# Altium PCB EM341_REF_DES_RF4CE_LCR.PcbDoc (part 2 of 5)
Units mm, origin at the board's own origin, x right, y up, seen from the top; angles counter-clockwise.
Board outline 218.38 x 83.13 mm, 2 copper layers (Top Layer, Carbon Ink Layer); 111 components, 91 nets, 369 pads, 80 vias.
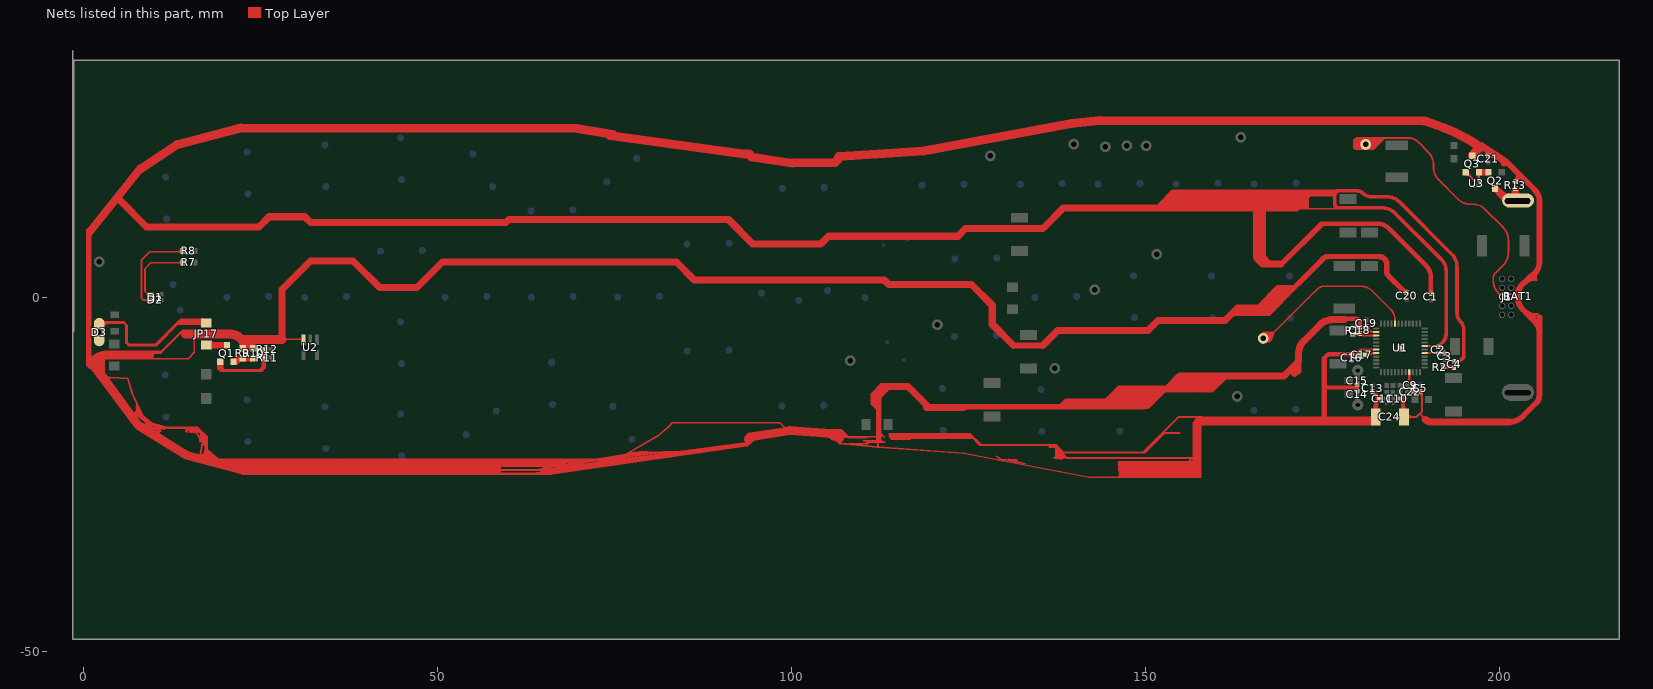
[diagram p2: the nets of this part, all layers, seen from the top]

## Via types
v1: diameter 1.2, hole 0, Top Layer to Carbon Ink Layer, 80 vias

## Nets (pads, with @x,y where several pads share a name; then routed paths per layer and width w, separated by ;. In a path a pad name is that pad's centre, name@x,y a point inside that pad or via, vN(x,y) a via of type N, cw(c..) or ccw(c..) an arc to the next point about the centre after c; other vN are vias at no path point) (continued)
1V8_39: C18.1 R1.2 U1.39 | length 6.6
  Top Layer w0.292: R1.2@179.19,-5.238 179.19,-5.242 cw(c179.419,-5.472) 179.419,-5.148 180.218,-5.148 cw(c180.218,-5.558) 180.508,-5.268 180.563,-5.323 ccw(c180.81,-5.075) 180.81,-5.425 U1.39@182.528,-5.425 ; R1.2@179.382,-5.352 cw(c179.874,-5.844) 179.874,-5.148 ccw(c179.874,-5.844) R1.2@179.382,-5.352 ; 179.829,-5.148 ccw(c179.829,-4.759) 180.104,-5.034 cw(c179.829,-4.759) 179.829,-5.148 ; 179.853,-5.148 cw(c179.853,-5.502) 180.104,-5.251 ccw(c179.853,-5.502) 179.853,-5.148 ; C18.1@180.255,-5.315 cw(c180.369,-5.711) 180.66,-5.42 ccw(c180.369,-5.711) C18.1@180.255,-5.315
BATT_NEG: BAT1.2 pad.51 pad.52 pad.53 pad.54 pad.55 pad.56 pad.57 pad.58 pad.59 pad.60 pad.61 pad.62 pad.63 pad.64 pad.65 pad.66 pad.67 pad.68 pad.69 pad.70 pad.71 pad.72 pad.73 pad.74 pad.75 pad.76 pad.77 pad.78 pad.79 pad.80 pad.81 pad.82 pad.83 pad.84 pad.85 pad.86 pad.87 pad.88 Q2.3 R13.2 | length 47.1
  Top Layer w1.016: Q2.3@199.308,15.388 200.319,14.376 ccw(c202.115,16.172) 202.115,13.632 BAT1.2@202.167,13.632 ; 200.044,14.651 ccw(c201.317,15.924) BAT1.2@201.317,14.124 ; BAT1.2@201.389,13.488 ccw(c200.266,15.022) R13.2@202.168,15.022 ; BAT1.2@201.498,13.496 ccw(c200.091,15.022) R13.2@202.168,15.022 ; BAT1.2@202.102,13.49 ccw(c201.946,13.647) BAT1.2@202.167,13.632 ; BAT1.2@202.567,13.632 202.475,13.632 202.25,13.632 BAT1.2@202.167,13.632 ; BAT1.2@202.772,14.079 cw(c203.206,15.022) R13.2@202.168,15.022 ; BAT1.2@202.881,13.492 cw(c204.166,15.022) R13.2@202.168,15.022 ; BAT1.2@201.826,13.499 ccw(c201.003,14.322) BAT1.2@202.168,14.322 ; BAT1.2@201.826,13.499 ccw(c201.003,14.322) BAT1.2@202.168,14.322 ; BAT1.2@201.826,13.499 ccw(c201.003,14.322) BAT1.2@202.168,14.322 ; BAT1.2@201.826,13.499 ccw(c201.003,14.322) BAT1.2@202.168,14.322 ; BAT1.2@202.167,13.632 ccw(c201.946,13.647) 202.168,13.647 R13.2@202.168,15.022 ; 200.446,14.249 ccw(c200.919,14.721) 201.148,14.094 cw(c200.919,14.721) 200.446,14.249 ; BAT1.2@201.576,13.499 ccw(c200.149,14.926) 202.168,14.926 cw(c200.149,14.926) BAT1.2@201.576,13.499 ; BAT1.2@201.651,13.499 ccw(c200.405,14.745) 202.168,14.745 cw(c200.405,14.745) BAT1.2@201.651,13.499 ; BAT1.2@201.676,13.499 ccw(c200.491,14.684) 202.168,14.684 cw(c200.491,14.684) BAT1.2@201.676,13.499 ; BAT1.2@201.751,13.499 ccw(c200.747,14.503) 202.168,14.503 cw(c200.747,14.503) BAT1.2@201.751,13.499 ; BAT1.2@201.776,13.499 ccw(c200.832,14.443) 202.168,14.443 cw(c200.832,14.443) BAT1.2@201.776,13.499 ; BAT1.2@201.951,13.499 ccw(c201.43,14.02) 202.168,14.02 cw(c201.43,14.02) BAT1.2@201.951,13.499 ; BAT1.2@202.001,13.499 ccw(c201.6,13.9) 202.168,13.9 cw(c201.6,13.9) BAT1.2@202.001,13.499 ; BAT1.2@202.168,14.057 ccw(c202.957,14.057) 202.399,13.499 cw(c202.957,14.057) BAT1.2@202.168,14.057 ; BAT1.2@202.168,14.238 ccw(c203.213,14.238) 202.474,13.499 cw(c203.213,14.238) BAT1.2@202.168,14.238 ; BAT1.2@202.168,14.479 ccw(c203.554,14.479) 202.574,13.499 cw(c203.554,14.479) BAT1.2@202.168,14.479 ; BAT1.2@202.168,14.6 ccw(c203.725,14.6) 202.624,13.499 cw(c203.725,14.6) BAT1.2@202.168,14.6 ; 202.168,14.781 ccw(c203.981,14.781) 202.699,13.499 cw(c203.981,14.781) 202.168,14.781 ; 202.168,14.841 ccw(c204.066,14.841) 202.724,13.499 cw(c204.066,14.841) 202.168,14.841
  Top Layer w1.27: BAT1.2@200.999,13.595 201.15,13.595 BAT1.2@201.335,13.595
GND: C1.2 C2.2 C3.2 C4.2 C5.2 C9.2 C10.2 C11.2 C13.2 C14.2 C15.2 C16.2 C17.2 C18.2 C19.2 C20.2 C21.2 C22.2 C24.1 C24.2 J1.5 Q3.3 R9.1 R10.1 R13.1 U1.9 U1.19 U1.38 U1.43 U1.49 U2.3 | length 2771.9
  Top Layer w0.254: 0.5,-9.56 0.44,-8.93 0.65,-9.64 1.17,-10.07 ; 0.5,9.47 7.73,18.45 ; 0.69,9.37 7.92,18.35 ; 0.72,8.5 0.834,8.756 ; 0.81,9.38 8.04,18.36 ; 0.83,9.28 8.06,18.26 ; 0.92,9.22 8.15,18.2 ; 1.02,9.2 8.25,18.18 ; 1.03,8.71 5.047,13.748 7.83,17.24 13.14,21.22 ; 1.62,10.05 0.86,9.37 3.75,12.75 ; 1.78,-9.24 1.91,-9.8 ; 2.01,-9.24 2.02,-10.01 ; 2.19,-9.01 2.27,-10.29 ; 2.44,-8.84 2.48,-10.6 ; 2.65,-8.8 2.67,-10.84 ; 2.88,-11.36 2.88,-8.7 ; 3.04,-11.38 3.74,-11.36 6.23,-11.52 6.82,-13.48 8.25,-16.61 9.53,-17.76 11.704,-18.432 ; 3.85,13.19 0.72,9.373 5.16,14.93 ; 4.38,12.97 0.834,8.756 ; 7.07,-8.197 7.342,-8.197 7.85,-7.69 10.97,-7.69 13.94,-4.72 14.61,-4.72 ; 7.47,-15.19 7.579,-15.485 ; 8.11,18.119 4.82,13.926 0.93,8.97 0.834,8.756 ; 8.82,-8.7 14.75,-8.7 15.64,-7.81 15.64,-6.01 16.427,-5.223 16.77,-5.223 ; 9.34,-7.9 10.93,-7.9 13.89,-4.94 ; 14.735,-18.602 16.112,-18.602 17.2,-19.69 17.2,-20.998 16.76,-20.558 16.76,-19.41 17.06,-19.71 17.06,-20.08 16.93,-19.95 16.93,-19.8 16.81,-19.68 ; 16.17,-18.84 16.49,-19.16 ; 16.43,-18.84 15.124,-18.84 14.957,-18.673 ; 16.798,-20.168 17.02,-20.39 ; 17.032,-19.31 17.412,-19.69 ; 17.2,-22.08 17.11,-21.57 17.06,-22.08 17.254,-22.358 ; 17.26,-21.321 17.412,-21.473 ; 17.328,-22.006 17.553,-22.444 ; 17.51,-22.96 17.448,-22.637 ; 17.59,-22.84 17.448,-22.637 ; 17.69,-22.71 17.553,-22.444 ; 18.534,-22.92 73.548,-22.92 ; 19.64,-23.08 36.12,-23.08 36.82,-23.78 21.13,-23.78 20.43,-23.08 ; 20.622,-23.272 36.032,-23.272 36.43,-23.67 21.71,-23.67 21.48,-23.44 21.29,-23.44 21.14,-23.29 21.14,-23.44 21.17,-23.47 36.04,-23.47 ; 21.36,-23.9 22.43,-24.97 66.083,-24.97 ; 27.85,-5.967 U2.3@31.054,-5.967 ; 36.16,-22.92 37.42,-24.18 37.94,-24.18 ; 36.48,-22.92 37.17,-23.61 38.84,-23.61 39.37,-23.08 ; 36.64,-23.08 71.766,-23.08 ; 36.838,-23.412 39.038,-23.412 ; 36.864,-23.304 39.146,-23.304 ; 37.1,-23.73 39.02,-23.73 39.41,-23.34 69.853,-23.34 ; 39.07,-23.78 67.224,-23.78 ; 39.19,-23.54 68.142,-23.54 ; 39.45,-23.22 69.893,-23.22 ; 57.04,-24.41 57.993,-24.767 ; 57.09,-24.41 57.09,-24.39 57.58,-23.9 67.749,-23.9 68.18,-23.77 76.325,-22.365 ; 57.36,-24.53 57.812,-24.7 57.993,-24.767 ; 57.47,-24.83 57.993,-24.767 ; 58.17,-24.66 58.4,-24.89 64.94,-24.89 ; 58.23,-24.41 64.49,-24.41 ; 58.41,-24.91 58.16,-24.83 57.993,-24.767 ; 64.01,-24.41 65.242,-24.13 ; 64.012,-24.838 91.85,-20.85 ; 64.75,-24.5 65.2,-24.76 71.435,-23.88 ; 64.854,-24.56 75.63,-23.12 83.85,-22.01 ; 64.96,-24.02 65.242,-24.13 ; 64.969,-24.898 65.18,-24.9 71.435,-23.88 ; 64.99,-24.92 64.49,-24.41 ; 65.066,-24.334 65.912,-24.968 93.75,-20.98 94.8,-20.09 ; 65.912,-24.868 93.75,-20.88 ; 69.47,-24.31 73.07,-23.83 ; 70.44,-23.38 75.847,-22.643 ; 72.66,-23.2 75.65,-22.758 ; 75.59,-22.793 75.65,-22.758 ; 79.11,-21.79 78.482,-21.895 ; 94.01,-20.53 64.49,-24.41 ; 94.45,-20.23 93.82,-20.72 88.087,-21.529 ; 99.26,-18.67 98.34,-17.75 83.15,-17.75 82.61,-18.29 81.17,-19.55 76.589,-22.212 ; 104.59,-19.194 104.906,-19.194 105.34,-18.76 107.01,-18.76 107.99,-19.74 ; 105.13,-19.79 105.84,-19.79 106.721,-20.671 107.034,-20.671 ; 106.26,-20.17 106.83,-20.65 107.034,-20.671 ; 106.74,-19.883 107,-19.51 107.99,-19.74 ; 106.96,-19.87 107.3,-19.76 107.98,-19.86 110.6,-19.88 ; 107.16,-19.4 106.89,-19.13 105.9,-19.13 105.71,-18.94 106.88,-18.94 107.5,-19.56 107.66,-19.56 ; 108.17,-20.71 110.77,-20.71 ; 110.1,-20.29 112.7,-20.29 ; 110.528,-20.478 113.128,-20.478 ; 111.45,-15.24 111.45,-13.61 ; 111.48,-13.61 112.73,-12.36 112.9,-12.36 ; 111.57,-15.23 111.83,-15.23 111.98,-15.08 111.98,-13.28 111.74,-13.52 111.74,-15.57 ; 111.62,-15.3 111.62,-13.67 ; 111.88,-15.63 111.88,-14 ; 111.98,-15.86 111.26,-15.14 111.26,-13.62 112.63,-12.25 113.32,-12.25 ; 112.07,-20.24 112.078,-20.29 112.108,-20.478 112.2,-21.05 ; 112.1,-19.74 107.99,-19.74 ; 112.24,-19.09 112.37,-19.09 113.04,-19.76 ; 112.45,-19.4 112.635,-19.585 112.865,-19.585 ; 112.505,-14.235 113.94,-12.8 114.85,-12.8 115.02,-12.63 ; 113.76,-19.36 125.228,-19.36 126.74,-20.872 126.74,-20.91 ; 113.81,-19.56 125.278,-19.56 ; 113.82,-19.65 125.288,-19.65 ; 113.83,-19.72 125.298,-19.72 ; 113.88,-19.79 125.348,-19.79 ; 113.92,-19.86 125.388,-19.86 ; 113.96,-19.93 125.428,-19.93 ; 114.09,-20.07 116.69,-20.07 ; 114.36,-19.86 116.96,-19.86 ; 114.36,-19.62 116.96,-19.62 ; 114.44,-19.45 117.04,-19.45 ; 125.42,-19.76 126.57,-20.91 137.38,-20.91 138.44,-21.97 149.86,-21.97 152.65,-19.18 154.74,-19.18 ; 128.91,-22.49 129.56,-22.94 130.18,-22.98 132.98,-23.54 130.59,-22.9 131.77,-23 ; 136.42,-21.19 137.15,-21.19 138.73,-22.77 ; 136.96,-22.7 138.46,-22.7 ; 137.11,-20.91 138.93,-22.73 156.985,-22.73 ; 137.336,-22.824 137.336,-21.376 ; 137.56,-22.83 137.56,-21.52 ; 137.705,-15.445 138.64,-14.51 ; 137.801,-22.779 137.801,-21.601 ; 137.95,-22.85 137.95,-21.94 ; 138.081,-22.689 138.081,-21.881 ; 138.22,-22.78 138.22,-22.22 ; 138.297,-15.096 141.012,-15.096 ; 138.396,-14.886 141.112,-14.886 ; 138.89,-15.5 144.86,-15.5 145.48,-14.88 ; 138.89,-14.9 144.44,-14.9 146.62,-12.72 ; 138.92,-15.29 144.83,-15.29 147.53,-12.59 ; 138.97,-15.72 144.83,-15.72 145.56,-14.99 ; 139.03,-14.7 144.35,-14.7 146.34,-12.71 ; 139.09,-15.11 144.75,-15.11 146.47,-13.39 146.47,-13.34 147.11,-12.7 ; 139.18,-14.51 144.28,-14.51 146.2,-12.59 152.82,-12.59 ; 140.53,-15.5 140.74,-15.29 ; 144.5,-15.11 146.83,-12.78 ; 145.64,-14.88 145.64,-14.37 147.26,-12.75 ; 146.13,-24.17 157.598,-24.17 ; 146.15,-23.7 157.618,-23.7 ; 146.15,-23.53 157.618,-23.53 ; 146.15,-23.4 157.618,-23.4 ; 146.15,-23.31 157.618,-23.31 ; 146.17,-24.01 157.638,-24.01 ; 146.17,-23.81 157.638,-23.81 ; 146.21,-24.56 157.678,-24.56 ; 146.21,-24.36 157.678,-24.36 ; 146.25,-25.31 157.718,-25.31 ; 146.25,-25.16 157.718,-25.16 ; 146.25,-24.96 157.718,-24.96 ; 146.28,-24.75 157.748,-24.75 ; 146.89,-14.81 146.89,-12.59 ; 149.55,-21.97 154.57,-16.95 157.98,-16.95 ; 153.87,-25.44 156.82,-22.49 157.225,-22.49 ; 157.007,-25.2 ccw(c157.481,-24.853) 157.827,-25.327 ; 157.518,-25.44 141.95,-25.44 124.24,-22.07 112.06,-21.19 107.034,-20.671 ; 169.22,4.31 175.29,10.38 176.27,10.38 ; 169.31,12.46 177.95,12.46 178.18,12.69 178.31,12.69 ; 170.25,12.46 172.6,14.81 172.9,14.81 ; 170.266,12.346 172.786,14.866 ; 170.462,12.672 170.932,12.672 ; 170.666,12.426 173.186,14.946 ; 170.702,12.672 172.84,14.81 ; 170.89,13.31 ccw(c170.98,13.89) 171.56,13.8 ; 171.025,12.445 173.575,14.995 ; 171.08,13.31 ccw(c171.17,13.89) 171.75,13.8 ; 171.33,13.28 ccw(c171.42,13.86) 172,13.77 ; 171.39,12.46 173.91,14.98 ; 171.62,12.46 172.72,13.56 172.72,12.59 172.71,12.6 172.05,12.6 172.57,13.12 ; 171.7,13.27 ccw(c171.79,13.85) 172.37,13.76 ; 171.84,13.15 ccw(c171.93,13.73) 172.51,13.64 ; 171.93,12.98 ccw(c172.02,13.56) 172.6,13.47 ; 171.94,12.69 ccw(c172.03,13.27) 172.61,13.18 ; 172.03,13.28 ccw(c172.12,13.86) 172.7,13.77 ; 172.04,12.57 ccw(c172.13,13.15) 172.71,13.06 ; 172.22,13.14 ccw(c172.31,13.72) 172.89,13.63 ; 172.46,13.01 172.46,12.82 172.56,12.72 172.56,12.87 ; 172.9,12.51 172.9,14.69 ; 172.9,14.77 173.17,15.04 ; 177.492,15.11 177.61,14.992 178.34,14.992 ; 188.823,-16.358 ccw(c189.523,-16.358) 189.028,-16.853 189.462,-17.287 ; R13.1@202.197,16.279 202.879,16.961 cw(c203.015,16.826) 203.015,17.017 ; 205.21,2.416 ccw(c205.178,0.017) 205.368,-2.376 ; 7.579,-15.485 7.966,-16.507 ; 7.579,-15.485 7.43,-15.58 7.9,-16.75 7.45,-16.04 7.45,-16.39 7.64,-16.69 7.21,-16.29 7.45,-16.61 9.28,-18.02 10.013,-18.248 ; 7.579,-15.485 7.95,-16.49 7.966,-16.507 ; 7.966,-16.507 8.5,-17.08 9.25,-17.8 11.6,-18.58 10.795,-18.6 ; 7.966,-16.507 8.16,-17.02 8.94,-17.64 10.245,-18.321 ; 10.013,-18.248 10.245,-18.321 ; 10.013,-18.248 10.523,-18.653 ; 10.013,-18.248 10.412,-18.712 ; 10.245,-18.321 10.82,-18.5 10.795,-18.6 ; 10.245,-18.321 10.78,-18.6 10.795,-18.6 ; 10.412,-18.712 10.583,-18.791 ; 10.412,-18.712 8.75,-17.94 10.66,-19.15 10.689,-19.033 ; 10.412,-18.712 10.689,-19.033 ; 10.523,-18.653 10.74,-18.825 ; 10.523,-18.653 10.583,-18.791 ; 10.583,-18.791 10.731,-18.86 ; 10.583,-18.791 10.689,-19.033 ; 10.689,-19.033 10.731,-18.86 ; 10.731,-18.86 10.86,-18.92 10.74,-18.825 ; 10.731,-18.86 10.74,-18.825 ; 10.74,-18.825 10.795,-18.6 ; 11.704,-18.432 11.86,-18.48 14.57,-18.55 14.957,-18.673 ; 11.704,-18.432 16.154,-18.432 17.412,-19.69 ; 14.957,-18.673 15.483,-18.84 16.49,-19.16 ; 15.627,-19.109 15.97,-19.22 16.46,-20.085 ; 15.627,-19.109 14.45,-18.73 14.45,-19.03 15.627,-19.109 ; 16.46,-20.085 16.62,-20.34 16.44,-20.44 16.46,-20.085 ; 16.46,-20.085 16.49,-19.54 16.76,-20.18 16.84,-20.37 16.794,-20.592 16.47,-22.15 16.77,-22.22 17.254,-22.358 ; 16.49,-19.16 16.76,-19.787 17.02,-20.39 ; 17.02,-20.39 17.121,-20.919 17.188,-21.271 ; 17.188,-21.271 17.408,-21.469 ; 17.188,-21.271 17.403,-22.401 ; 17.254,-22.358 17.403,-22.401 ; 17.254,-22.358 17.448,-22.637 ; 17.403,-22.401 17.448,-22.637 ; 17.403,-22.401 17.553,-22.444 ; 17.408,-21.469 17.412,-21.473 ; 17.408,-21.469 17.6,-22.23 17.908,-22.545 ; 17.408,-21.469 18.202,-22.349 ; 17.412,-21.473 19.021,-22.92 19.31,-23.18 18.959,-22.92 18.584,-22.642 ; 17.412,-21.473 17.412,-19.69 ; 17.553,-22.444 17.908,-22.545 ; 17.908,-22.545 18.241,-22.641 ; 17.908,-22.545 18,-22.64 18.241,-22.641 ; 18.202,-22.349 18.23,-22.38 18.584,-22.642 ; 18.202,-22.349 18.584,-22.642 ; 18.202,-22.349 17.63,-21.91 18.241,-22.641 ; 18.241,-22.641 18.584,-22.642 ; 30.529,-5.967 cw(c30.529,-6.562) U2.3@30.949,-6.142 ; 30.529,-5.967 cw(c30.529,-6.562) U2.3@30.949,-6.142 ; 30.529,-5.967 cw(c30.529,-6.562) U2.3@30.949,-6.142 ; 30.529,-5.967 cw(c30.529,-6.562) U2.3@30.949,-6.142 ; 65.242,-24.13 65.55,-24.06 66.506,-23.9 67.224,-23.78 ; 67.224,-23.78 71.404,-23.08 76.589,-22.212 ; 71.435,-23.88 88.087,-21.529 ; 71.435,-23.88 78.79,-23.01 87.3,-21.77 88.087,-21.529 ; 75.65,-22.758 75.847,-22.643 ; 75.65,-22.758 80.134,-22.095 ; 75.847,-22.643 76.325,-22.365 ; 75.847,-22.643 79.32,-22.17 80.134,-22.095 ; 76.325,-22.365 76.589,-22.212 ; 76.325,-22.365 78.783,-21.942 ; 76.589,-22.212 78.094,-21.96 ; 78.094,-21.96 78.783,-21.942 ; 78.094,-21.96 77.344,-21.98 78.482,-21.895 ; 78.094,-21.96 78.482,-21.895 ; 78.482,-21.895 79.488,-21.82 78.783,-21.942 ; 78.783,-21.942 78.976,-21.936 ; 78.976,-21.936 79.236,-21.972 ; 78.976,-21.936 79.97,-21.91 83.66,-21.77 80.134,-22.095 ; 78.976,-21.936 77.57,-22.26 79.236,-21.972 ; 79.236,-21.972 80.134,-22.095 ; R13.1@202.247,16.477 ccw(c202.247,16.834) 202.5,16.582 cw(c202.247,16.834) R13.1@202.247,16.477 ; R13.1@202.445,16.279 cw(c203.044,16.279) 202.62,16.702 ccw(c203.044,16.279) R13.1@202.445,16.279
  Top Layer w0.292: C17.2@180.035,-8.145 180.035,-7.677 cw(c180.209,-7.677) 180.086,-7.554 cw(c180.398,-7.866) 180.398,-7.425 U1.43@182.528,-7.425 ; C18.2@180.312,-4.415 cw(c180.355,-4.457) C18.2@180.355,-4.397 ; U1.38@182.528,-4.925 182.122,-4.925 cw(c182.122,-4.148) 181.572,-4.697 181.409,-4.534 ccw(c181.345,-4.598) 181.345,-4.507 181.312,-4.507 cw(c181.312,-4.286) 181.155,-4.443 ccw(c181.046,-4.551) 181.046,-4.397 C18.2@180.355,-4.397 ; C24.1@186.418,-16.927 188.223,-16.927 189.015,-16.135 189.015,-13.587 188.73,-13.303 188.73,-13.273 187.893,-13.273 187.838,-13.217 187.838,-12.512 187.618,-12.293 187.618,-12.025 ; U1.9@187.199,-10.497 187.199,-11.607 187.618,-12.025 ; U1.19@189.378,-6.925 191.24,-6.925 cw(c191.24,-7.01) C2.2@191.3,-6.95 ; C2.2@191.333,-6.989 cw(c191.293,-7.7) 191.796,-7.196 191.972,-7.372 cw(c191.417,-7.927) C3.2@192.202,-7.927 ; C18.2@180.355,-4.397 ccw(c180.355,-3.617) 180.99,-4.071 cw(c180.355,-3.617) C18.2@180.355,-4.397 ; C24.1@186.826,-17.306 cw(c187.739,-18.219) 187.739,-16.927 ; C24.1@186.826,-17.306 cw(c187.739,-18.219) 187.739,-16.927 ; C24.1@186.826,-17.306 cw(c187.739,-18.219) 187.739,-16.927 ; C24.1@186.826,-16.522 ccw(c187.804,-15.544) 187.804,-16.927 ; C24.1@186.826,-16.522 ccw(c187.804,-15.544) 187.804,-16.927 ; C24.1@186.826,-16.522 ccw(c187.804,-15.544) 187.804,-16.927 ; 187.618,-12.025 ccw(c187.942,-12.025) C9.2@187.827,-12.328 ; 187.618,-12.025 ccw(c187.942,-12.025) C9.2@187.827,-12.328 ; 187.618,-12.025 ccw(c187.942,-12.025) C9.2@187.827,-12.328 ; C22.2@187.713,-13.265 ccw(c187.412,-12.964) 187.838,-12.964 ; C22.2@187.713,-13.265 ccw(c187.412,-12.964) 187.838,-12.964 ; C22.2@187.713,-13.265 ccw(c187.412,-12.964) 187.838,-12.964 ; C9.2@187.713,-12.581 cw(c187.413,-12.881) 187.838,-12.881 ; C9.2@187.713,-12.581 cw(c187.413,-12.881) 187.838,-12.881 ; C9.2@187.713,-12.581 cw(c187.413,-12.881) 187.838,-12.881 ; 187.838,-13.04 ccw(c188.155,-13.04) C22.2@187.931,-13.265 ; 187.838,-13.04 ccw(c188.155,-13.04) C22.2@187.931,-13.265 ; 187.838,-13.04 ccw(c188.155,-13.04) C22.2@187.931,-13.265 ; 187.838,-12.806 cw(c188.156,-12.806) C9.2@187.931,-12.581 ; 187.838,-12.806 cw(c188.156,-12.806) C9.2@187.931,-12.581 ; 187.838,-12.806 cw(c188.156,-12.806) C9.2@187.931,-12.581 ; C22.2@187.931,-13.483 cw(c188.438,-13.991) 188.438,-13.273 ; C22.2@187.931,-13.483 cw(c188.438,-13.991) 188.438,-13.273 ; C22.2@187.931,-13.483 cw(c188.438,-13.991) 188.438,-13.273 ; 188.314,-13.273 cw(c188.314,-13.728) C5.2@188.636,-13.406 ; 188.314,-13.273 cw(c188.314,-13.728) C5.2@188.636,-13.406 ; 188.314,-13.273 cw(c188.314,-13.728) C5.2@188.636,-13.406 ; 188.433,-13.273 ccw(c188.433,-12.985) C5.2@188.636,-13.188 ; 188.433,-13.273 ccw(c188.433,-12.985) C5.2@188.636,-13.188 ; 188.433,-13.273 ccw(c188.433,-12.985) C5.2@188.636,-13.188 ; C5.2@188.636,-13.456 cw(c187.722,-14.371) 189.015,-14.371 ; C5.2@188.636,-13.456 cw(c187.722,-14.371) 189.015,-14.371 ; C5.2@188.636,-13.456 cw(c187.722,-14.371) 189.015,-14.371 ; C5.2@188.843,-13.249 cw(c188.427,-13.665) 189.015,-13.665 ; C5.2@188.843,-13.249 cw(c188.427,-13.665) 189.015,-13.665 ; C5.2@188.843,-13.249 cw(c188.427,-13.665) 189.015,-13.665 ; C17.2@179.938,-8.036 ccw(c179.705,-7.803) 180.035,-7.803 cw(c179.705,-7.803) C17.2@179.938,-8.036 ; 180.035,-7.744 ccw(c180.449,-7.744) 180.156,-8.036 cw(c180.449,-7.744) 180.035,-7.744 ; C18.2@180.321,-4.159 ccw(c180.898,-3.582) 180.898,-4.397 cw(c180.898,-3.582) C18.2@180.321,-4.159 ; C19.2@180.922,-4.397 ccw(c180.922,-4.023) 181.227,-4.241 cw(c180.922,-4.023) C19.2@180.922,-4.397 ; C19.2@181.267,-4.183 ccw(c181.625,-4.238) 181.369,-4.494 cw(c181.625,-4.238) C19.2@181.267,-4.183 ; C19.2@181.269,-4.16 ccw(c181.833,-4.16) 181.434,-4.559 cw(c181.833,-4.16) C19.2@181.269,-4.16 ; 190.762,-6.925 cw(c190.762,-7.535) 191.193,-7.104 ccw(c190.762,-7.535) 190.762,-6.925
  Top Layer w0.4: 138.63,-14.7 145.01,-14.7 ; 138.74,-14.51 145.13,-14.51 ; 144.07,-15.03 150.45,-15.03 ; 144.27,-14.81 150.65,-14.81 ; 144.43,-14.61 150.81,-14.61 ; 144.62,-14.47 151,-14.47 ; 144.77,-14.33 151.15,-14.33 ; 144.92,-14.21 151.3,-14.21 ; 145.14,-14.04 151.52,-14.04 ; 145.39,-13.84 151.77,-13.84 ; 145.59,-13.62 151.97,-13.62 ; 145.81,-13.39 152.19,-13.39 ; 146.28,-13.09 152.66,-13.09 ; 146.4,-12.83 152.78,-12.83
  Top Layer w0.508: 175.178,-12.77 179.85,-12.77 ; 176.6,14.69 176.902,14.992 179.828,14.992 cw(c179.828,13.808) 180.665,14.645 ccw(c181.83,15.81) 181.83,14.162 184.05,14.162 cw(c184.05,11.622) 185.846,13.419 193.2,6.065 cw(c191.404,4.269) 193.944,4.269 193.944,-2.224 ccw(c195.699,-2.224) 194.458,-3.465 cw(c193.407,-4.516) 194.893,-4.516 194.893,-8.313 cw(c194.388,-8.313) 194.745,-8.67 cw(c193.847,-7.772) 193.847,-9.042 C4.2@193.53,-9.042 ; 177.224,14.992 ccw(c177.224,14.611) 176.955,14.88 ccw(c177.589,14.246) 176.692,14.246 176.692,13.094 ccw(c177.222,13.094) 176.848,12.72 ccw(c177.173,13.046) 177.173,12.585 183.405,12.585 cw(c183.405,10.045) 185.201,11.841 191.747,5.296 cw(c190.169,3.718) 192.401,3.718 192.401,-5.187 cw(c190.628,-5.187) 191.881,-6.441 C2.2@191.302,-7.02 ; C16.2@179.085,-8.105 ccw(c179.185,-8) 179.185,-8.145 C17.2@180.035,-8.145 ; C15.2@179.857,-12.283 179.857,-13.275 C14.2@179.89,-13.275 ; C18.2@180.212,-4.242 180.851,-4.242 ccw(c180.851,-3.876) C19.2@181.11,-4.135 ; C10.2@185.926,-14.34 186.325,-14.34 186.325,-16.853 C24.1@186.48,-16.853 ; 180.806,-4.242 ccw(c180.806,-3.851) 181.082,-4.128 cw(c180.806,-3.851) 180.806,-4.242 ; C10.2@185.918,-14.373 cw(c184.937,-15.354) 186.325,-15.354 ccw(c184.937,-15.354) C10.2@185.918,-14.373 ; C24.1@186.119,-16.099 ccw(c185.62,-15.6) 186.325,-15.6 cw(c185.62,-15.6) C24.1@186.119,-16.099 ; 186.325,-15.074 ccw(c187.774,-15.074) 186.749,-16.099 cw(c187.774,-15.074) 186.325,-15.074
  Top Layer w0.635: 148.63,-15.51 150.28,-15.51 152.75,-13.04 ; 169.08,4.68 174.78,10.38 181.618,10.38 ; 175.178,-8.725 cw(c175.36,-8.725) 175.231,-8.596 175.593,-8.233 cw(c175.904,-8.544) 175.904,-8.105 C16.2@179.098,-8.105 ; 178.084,-3.19 ccw(c177.948,-2.741) 178.28,-3.073 179.612,-3.073 cw(c179.612,-3.929) 180.218,-3.323 ; C18.2@180.235,-4.242 180.235,-3.323 ; 181.372,10.372 182.595,10.372 cw(c182.595,7.832) 184.391,9.629 189.511,4.509 cw(c187.715,2.713) 190.255,2.713 C1.2@190.255,0.468 ; C13.2@182.027,-13.343 182.967,-14.282 cw(c182.941,-14.307) 182.977,-14.307 ccw(c184.227,-15.557) 182.46,-15.557 ; C24.2@182.46,-16.963 182.46,-15.557 ; J1.5@201.585,0.025 202.295,0.025 ccw(c202.295,0.17) 202.398,0.068 ; R13.1@202.197,16.279 ccw(c201.321,17.155) 202.56,17.155 202.56,17.195 ; 182.46,-15.557 cw(c181.666,-15.557) 182.21,-16.135 ccw(c181.666,-15.557) 182.46,-15.557 ; 182.46,-15.557 ccw(c183.207,-15.557) 182.721,-16.124 cw(c183.207,-15.557) 182.46,-15.557
  Top Layer w0.762: 162.48,-2.26 167.363,-2.26 169.081,-0.542 ; 165.07,-1.522 166.048,-1.522 ; 166.02,-1.35 168.69,1.32 170.93,1.32 ; 166.24,-1.65 167.973,-1.65 175.011,5.387 cw(c175.832,4.566) 175.832,5.727 182.865,5.727 cw(c182.865,4.515) 183.723,5.372 cw(c183.022,4.672) 184.012,4.672 184.012,3.639 ccw(c184.911,3.639) 184.276,3.003 186.497,0.782 ccw(c186.78,1.066) C20.2@186.78,0.665 ; 166.67,-1.65 ccw(c166.67,0.89) 168.466,-0.906 ; 167.084,-1.046 168.668,0.538 ; 167.634,-0.986 169.218,0.598 ; 167.874,-0.416 169.458,1.168 ; 168.042,-0.578 169.626,1.006 ; 168.514,-0.686 170.098,0.898 ; 175.164,-17.492 ccw(c175.049,-17.434) 175.178,-17.434 175.178,-8.725
  Top Layer w0.78: 202.94,1.55 204.16,2.77
  Top Layer w0.8: 0.72,-8.86 0.72,9.373 ; 4.006,12.947 4.798,13.946 8.11,18.119 ; 112.31,-20.24 112.31,-13.65 ; 123.99,-15.51 149.75,-15.51 152.28,-12.98 ; 131.317,-6.843 135.447,-6.843 ; 200.999,19.041 204.942,15.098 cw(c203.355,13.51) 205.6,13.51 205.6,5.055 cw(c203.06,5.055) 204.856,3.259 ; 201.388,-17.628 ccw(c201.388,-15.088) 203.184,-16.884 205.12,-14.948 ccw(c203.985,-13.813) 205.59,-13.813 205.59,-2.85 ; 202.5,0.38 cw(c204.082,0.38) 202.963,1.498 ; 202.5,0.39 202.511,0.166 ; 202.515,0.015 ccw(c205.055,0.015) 203.259,-1.781 204.846,-3.369 cw(c203.05,-5.165) 205.59,-5.165 ; 203.652,-2.177 ccw(c204.77,-1.058) 204.77,-2.64 ; 203.696,2.248 cw(c204.814,1.129) 204.814,2.711
  Top Layer w0.965: 204.344,2.746 204.856,3.259 ; 204.49,2.78 ccw(c204.066,3.49) 204.651,2.905
  Top Layer w1: 5.047,13.748 8.885,9.91 24.78,9.91 26.21,11.34 31.23,11.34 32.03,10.54 59.63,10.54 60.07,10.98 91.03,10.98 94.5,7.51 104.09,7.51 105.17,8.59 123.46,8.59 124.56,9.69 135.46,9.69 138.37,12.6 171.29,12.6 ; 28.02,-5.967 28.02,1.09 32.03,5.1 38.06,5.1 41.82,1.34 47.07,1.34 50.68,4.95 83.71,4.95 86.28,2.38 113.06,2.38 113.69,1.75 125.4,1.75 128.31,-1.16 128.31,-3.836 131.317,-6.843 ; 112.31,-13.65 113.33,-12.63 116.41,-12.63 119.33,-15.55 ; 119.02,-15.61 124.23,-15.61 ; 135.447,-6.843 137.57,-4.72 150.29,-4.72 151.712,-3.298 161.202,-3.298 162.978,-1.522 167.049,-1.522 ; 149.942,-15.318 152.28,-12.98 152.98,-12.98 154.8,-11.16 169.5,-11.16 ; 152.14,12.95 153.88,14.69 176.6,14.69 ; 153.06,-12.98 159.3,-12.98 160.93,-11.35 ; 153.08,13.2 171.32,13.2 ; 153.54,-12.44 159.78,-12.44 ; 153.83,13.91 172.134,13.91 ; 154.14,-11.82 160.38,-11.82 ; 165.62,13.27 165.62,5.56 166.5,4.68 169.08,4.68 ; 166.44,12.22 166.44,5.61 167.37,4.68 ; 169.579,-11.091 171.499,-9.171 ccw(c168.525,-8.505) 171.572,-8.505 171.572,-7.987 cw(c174.112,-7.987) 172.302,-6.206 ; 171.015,-10.775 171.15,-10.64 ; 171.36,-9.468 171.499,-9.329 171.42,-9.25 ; 171.49,-10.46 171.49,-9.148 ; 172.316,-6.191 174.574,-3.934 cw(c176.37,-5.73) 176.37,-3.19 178.084,-3.19 ; 200.743,19.11 200.78,19.11
  Top Layer w1.016: 189.462,-17.287 ccw(c190.283,-16.467) 190.283,-17.628 201.388,-17.628 ; 197.274,21.414 197.543,21.263 198.711,20.503 ; 198.679,20.513 200.548,19.298 200.62,18.96 ; C21.2@198.332,20.256 cw(c198.71,19.751) 199.054,20.28 ; C21.2@198.332,20.256 cw(c198.71,19.751) 199.054,20.28 ; C21.2@198.332,20.256 cw(c198.71,19.751) 199.054,20.28 ; C21.2@198.332,20.256 cw(c198.71,19.751) 199.054,20.28 ; C21.2@198.313,20.136 cw(c198.685,18.382) 199.662,19.885 ccw(c198.685,18.382) C21.2@198.313,20.136
  Top Layer w1.27: 8.11,18.119 13.179,21.508 22.194,23.879 69.654,23.791 74.784,22.974 74.307,22.817 93.231,20.227 93.985,20.205 94.287,19.794 100.125,18.897 106.143,18.991 106.465,19.345 106.65,19.825 118.595,20.638 139.491,24.511 143.482,24.91 189.345,24.873 192.105,23.905 193.64,23.247 195.45,22.295 196.71,21.565 ; 9.293,-8.197 3.317,-8.197 ; 14.371,-5.223 20.577,-5.223 ; 22.355,-5.967 28.02,-5.967 ; 58.405,-24.41 22.457,-24.41 14.511,-22.324 7.745,-18.145 1.568,-9.807 1.017,-9.5 0.998,-9.474 0.994,-9.469 1.521,-8.941 ; 93.904,-20.045 94.102,-19.772 99.663,-18.878 104.59,-19.194 105.613,-19.26 105.905,-19.593 106.412,-19.793 106.74,-19.883 ; 157.177,-24.905 ccw(c157.177,-24.837) 157.225,-24.885 157.225,-18.084 ; C24.2@182.407,-16.9 cw(c182.009,-16.9) 182.291,-17.182 182.203,-17.27 cw(c181.665,-16.733) 181.665,-17.492 158.025,-17.492 ; Q3.3@196.116,19.97 196.93,20.999 197.04,20.999 ; 1.521,-8.941 cw(c3.317,-10.737) 3.317,-8.197 ; 1.521,-8.941 cw(c3.317,-10.737) 3.317,-8.197 ; 1.521,-8.941 cw(c3.317,-10.737) 3.317,-8.197 ; 20.577,-5.223 cw(c20.577,-7.636) 22.283,-5.93 ; 20.577,-5.223 cw(c20.577,-7.636) 22.283,-5.93 ; 22.283,-5.93 22.328,-5.976 ; 22.328,-5.976 cw(c21.522,-6.783) R9.1@22.662,-6.783 ; 22.328,-5.976 cw(c21.522,-6.783) R9.1@22.662,-6.783 ; R9.1@22.662,-6.783 ccw(c23.188,-6.257) 23.188,-7 ; R9.1@22.662,-6.783 ccw(c23.188,-6.257) 23.188,-7 ; 23.188,-7 23.468,-7 ; 23.468,-7 ccw(c23.468,-6.573) R10.1@23.77,-6.875 ; 23.468,-7 ccw(c23.468,-6.573) R10.1@23.77,-6.875 ; R10.1@23.77,-6.875 ccw(c23.686,-6.791) R10.1@23.805,-6.791 ; R10.1@23.77,-6.875 ccw(c23.686,-6.791) R10.1@23.805,-6.791 ; R10.1@23.805,-6.791 cw(c24.742,-6.791) 24.079,-6.128 ; R10.1@23.805,-6.791 cw(c24.742,-6.791) 24.079,-6.128 ; 24.079,-6.128 cw(c24.467,-6.516) 24.467,-5.967 ccw(c24.467,-6.516) 24.079,-6.128 ; 157.225,-18.084 cw(c157.669,-18.084) 157.355,-17.77 ; 157.225,-18.084 cw(c157.669,-18.084) 157.355,-17.77 ; 157.355,-17.77 cw(c158.025,-18.44) 158.025,-17.492 ; 157.355,-17.77 cw(c158.025,-18.44) 158.025,-17.492
JCLK: J1.6 pad.0@181.04,21.55 | length 79.2
  Top Layer w0.254: 179.413,21.48 pad.0@180.503,21.48 ; 179.453,21.65 pad.0@180.543,21.65 ; 179.473,21.25 pad.0@180.563,21.25 ; 179.483,21.8 pad.0@180.573,21.8 ; 179.513,21.94 pad.0@180.603,21.94 ; 179.593,21.08 pad.0@180.683,21.08 ; 179.593,22.11 pad.0@180.683,22.11 ; 179.633,22.28 180.723,22.28 ; pad.0@180.663,22.207 cw(c181.009,21.733) pad.0@181.483,22.08 ; pad.0@180.933,21.73 182.023,21.73 ; pad.0@181.03,21.65 181.835,22.455 ; pad.0@181.103,21.05 182.193,21.05 ; pad.0@181.193,21.92 182.283,21.92 ; pad.0@181.313,21.24 182.403,21.24 ; 181.333,22.29 182.423,22.29 ; pad.0@181.343,22.15 182.433,22.15 ; pad.0@181.443,21.39 182.533,21.39 ; 181.523,22.32 182.613,22.32 ; pad.0@181.544,21.134 182.857,22.447 ; pad.0@181.573,21.53 182.663,21.53 ; pad.0@181.723,21.66 182.813,21.66 ; 181.883,21.78 182.973,21.78 ; 181.973,21.89 183.063,21.89 ; 182.083,22.02 183.173,22.02 ; 182.098,22.455 179.705,22.455 179.38,22.13 179.38,21.09 179.61,20.86 182.09,20.86 183.673,22.443 ; 182.183,22.15 183.273,22.15 ; 182.223,22.27 183.313,22.27 ; J1.6@199.993,0.05 ccw(c199.395,0.097) 199.819,0.521 ccw(c200.243,0.945) J1.6@200.29,0.347 ; J1.6@200.315,0.025 199.819,0.521 cw(c201.615,2.317) 199.075,2.317 199.075,2.762 cw(c199.843,2.762) 199.3,3.305 200.461,4.466 ccw(c198.665,6.262) 201.205,6.262 201.205,8.034 ccw(c198.665,8.034) 200.461,9.83 197.814,12.477 ccw(c196.323,10.986) 196.323,13.095 195.88,13.095 cw(c195.88,15.635) 194.084,13.839 191.371,16.551 cw(c193.168,18.348) 190.628,18.348 190.628,18.675 ccw(c188.088,18.675) 189.884,20.471 188.592,21.763 188.58,21.763 188.39,21.953 ccw(c187.179,20.743) 187.179,22.455 181.835,22.455 ; 181.835,22.455 cw(c181.17,23.12) 181.092,22.183 ccw(c181.17,23.12) 181.835,22.455 ; 181.835,22.455 ccw(c182.355,21.935) 181.649,21.729 cw(c182.355,21.935) 181.835,22.455 ; pad.0@181.406,21.657 cw(c181.886,21.798) 181.532,22.152 ccw(c181.886,21.798) pad.0@181.406,21.657
JCLK_1: 
JCLK_2: 
JCLK_3: pad.0@166.58,-5.84 U1.32 | length 38.2
  Top Layer w0.254: pad.0@166.362,-5.288 166.68,-4.97 167.13,-4.97 ; pad.0@166.65,-6.32 167.11,-6.32 167.12,-6.31 167.45,-6.31 167.776,-5.984 167.776,-5.534 167.51,-5.8 167.51,-6.03 167.42,-6.12 167.45,-6.12 167.66,-5.91 ; pad.0@166.72,-5.1 cw(c166.63,-5.68) pad.0@167.21,-5.77 ; pad.0@166.78,-6.28 ccw(c166.87,-5.7) 167.45,-5.79 ; pad.0@167.21,-6.02 ccw(c167.3,-5.44) 167.88,-5.53 ; pad.0@167.25,-5.89 ccw(c167.34,-5.31) 167.92,-5.4 ; pad.0@167.31,-5.71 ccw(c167.4,-5.13) 167.98,-5.22 ; 167.38,-5.58 ccw(c167.47,-5) 168.05,-5.09 ; 167.61,-5.15 167.41,-5.35 167.41,-5.49 167.2,-5.28 167.2,-5.22 167.27,-5.15 167.85,-5.15 168.03,-4.97 167.13,-4.97 ; 167.66,-4.97 168.11,-4.97 ; 167.776,-5.75 167.776,-5.3 ; 173.03,-0.08 cw(c173.076,-0.08) 173.033,-0.064 ; U1.32@185.203,-3.75 185.203,-3.329 ccw(c182.879,-3.329) 184.523,-1.685 182.05,0.788 ccw(c180.254,-1.008) 180.254,1.532 175.218,1.532 ccw(c175.218,0.097) 174.203,1.112 173.044,-0.048 ccw(c173.076,-0.08) 173.033,-0.064 ; 167.13,-4.97 166.58,-5.52 pad.0@166.58,-5.84 167.257,-5.84 173.033,-0.064
NetC2_1: C2.1 U1.17 | length 3.8
  Top Layer w0.292: U1.17@189.378,-7.925 190.976,-7.925 ; C2.1@191.03,-7.902 cw(c190.976,-7.848) 190.976,-7.925 ; 190.976,-7.925 cw(c190.976,-8.203) 191.186,-8.021 ccw(c190.976,-8.203) 190.976,-7.925 ; 190.976,-7.925 ccw(c190.976,-7.664) 191.181,-7.825 cw(c190.976,-7.664) 190.976,-7.925 ; 190.918,-7.925 ccw(c190.918,-7.536) 191.193,-7.811 cw(c190.918,-7.536) 190.918,-7.925 ; 190.943,-7.925 cw(c190.943,-8.279) 191.193,-8.029 ccw(c190.943,-8.279) 190.943,-7.925
NetC4_1: C4.1 R2.2 | length 1.5
  Top Layer w0.508: R2.2@192.03,-9.881 C4.1@193.509,-9.881
NetC17_1: C17.1 U1.44 | length 2.4
  Top Layer w0.305: C17.1@180.947,-8.09 ccw(c180.99,-8.048) 180.99,-8.107 181.728,-8.107 cw(c182.168,-8.548) 182.168,-7.925 U1.44@182.528,-7.925 ; C17.1@181.077,-8.249 cw(c181.419,-8.592) 181.419,-8.107 ccw(c181.419,-8.592) C17.1@181.077,-8.249
NetD1_K: D1.2 R7.2 | length 13.2
  Top Layer w0.254: D1.2@9.45,0.4 9.08,0.4 8.67,0.81 8.67,4 9.51,4.84 14.01,4.84 R7.2@14.05,4.88 ; 8.805,0.675 ccw(c9.138,1.008) 9.293,0.563 cw(c9.138,1.008) 8.805,0.675 ; 13.248,4.84 ccw(c13.248,5.682) 13.843,5.087 cw(c13.248,5.682) 13.248,4.84 ; 13.441,4.84 cw(c13.441,4.271) 13.843,4.673 ccw(c13.441,4.271) 13.441,4.84
NetD2_K: D2.2 R8.2 | length 16.5
  Top Layer w0.254: 8.921,-0.4 D2.2@9.45,-0.4 8.42,-0.4 8.17,-0.15 8.17,5.21 9.35,6.39 13.91,6.39 R8.2@14.05,6.53 ; 13.007,6.39 ccw(c13.007,7.573) 13.843,6.737 cw(c13.007,7.573) 13.007,6.39 ; 13.62,6.39 ccw(c13.62,6.96) 14.023,6.557 cw(c13.62,6.96) 13.62,6.39
NetD3_K: D3.2 JP17.1 pad.1@2.2,-4.95 pad.2@2.2,-4.95 | length 116.3
  Top Layer w0.254: pad.2@2.25,-3.71 2.298,-3.662 5.16,-3.662 ; 4.99,-3.662 5.672,-3.662 6,-3.99 6,-6.49 6.36,-6.85 10.27,-6.85 13.458,-3.662 JP17.1@16.96,-3.662 ; 12.99,-3.85 13.7,-3.14 16.87,-3.14 17.37,-3.64 JP17.1@17.37,-3.662 ; 13.15,-3.85 17.2,-3.85 17.387,-3.662 17.56,-3.662 13.177,-3.662 10.81,-6.03 10.17,-6.67 6.4,-6.67 6.12,-6.39 6.12,-3.97 5.69,-3.54 3.02,-3.54 ; 13.596,-3.244 JP17.1@17.002,-3.244 ; 13.612,-3.52 13.612,-3.41 JP17.1@16.76,-3.41 ; pad.2@2.469,-3.981 cw(c3.535,-5.047) 3.535,-3.54 ccw(c3.535,-5.047) pad.2@2.469,-3.981 ; pad.2@2.469,-3.981 cw(c3.239,-4.751) 3.239,-3.662 ccw(c3.239,-4.751) pad.2@2.469,-3.981 ; pad.2@2.649,-4.161 cw(c4.148,-5.66) 4.148,-3.54 ccw(c4.148,-5.66) pad.2@2.649,-4.161 ; pad.2@2.649,-4.161 cw(c3.853,-5.365) 3.853,-3.662 ccw(c3.853,-5.365) pad.2@2.649,-4.161 ; pad.2@2.649,-3.263 ccw(c3.318,-2.594) 3.318,-3.54 cw(c3.318,-2.594) pad.2@2.649,-3.263 ; pad.2@2.649,-3.263 ccw(c3.614,-2.298) 3.614,-3.662 cw(c3.614,-2.298) pad.2@2.649,-3.263 ; 3.02,-3.54 cw(c3.02,-3.217) 2.744,-3.384 ccw(c3.02,-3.217) 3.02,-3.54 ; 3.02,-3.54 ccw(c3.02,-3.725) 2.835,-3.722 cw(c3.02,-3.725) 3.02,-3.54 ; 15.937,-3.662 cw(c15.937,-4.925) JP17.1@16.83,-4.032 ; 15.937,-3.662 ccw(c15.937,-2.4) JP17.1@16.83,-3.293 ; 15.937,-3.662 cw(c15.937,-4.925) JP17.1@16.83,-4.032 ; 15.937,-3.662 ccw(c15.937,-2.4) JP17.1@16.83,-3.293 ; 15.937,-3.662 ccw(c15.937,-2.4) JP17.1@16.83,-3.293 ; 15.937,-3.662 cw(c15.937,-4.925) JP17.1@16.83,-4.032 ; 15.937,-3.662 ccw(c15.937,-2.4) JP17.1@16.83,-3.293 ; 15.937,-3.662 cw(c15.937,-4.925) JP17.1@16.83,-4.032 ; JP17.1@16.83,-4.032 ccw(c14.676,-6.187) 14.676,-3.14 cw(c14.676,-6.187) JP17.1@16.83,-4.032 ; JP17.1@16.83,-4.032 ccw(c14.928,-5.934) 14.928,-3.244 cw(c14.928,-5.934) JP17.1@16.83,-4.032 ; JP17.1@16.83,-4.032 ccw(c15.328,-5.535) 15.328,-3.41 cw(c15.328,-5.535) JP17.1@16.83,-4.032 ; JP17.1@16.83,-4.032 ccw(c16.39,-4.472) 16.39,-3.85 cw(c16.39,-4.472) JP17.1@16.83,-4.032 ; JP17.1@16.83,-3.293 cw(c16.547,-3.009) 16.547,-3.41 ccw(c16.547,-3.009) JP17.1@16.83,-3.293 ; JP17.1@16.83,-3.293 cw(c15.485,-1.947) 15.485,-3.85 ccw(c15.485,-1.947) JP17.1@16.83,-3.293 ; JP17.1@17.01,-3.853 ccw(c15.289,-5.573) 15.289,-3.14 cw(c15.289,-5.573) JP17.1@17.01,-3.853 ; JP17.1@17.01,-3.853 ccw(c15.541,-5.321) 15.541,-3.244 cw(c15.541,-5.321) JP17.1@17.01,-3.853 ; JP17.1@17.01,-3.853 ccw(c15.941,-4.922) 15.941,-3.41 cw(c15.941,-4.922) JP17.1@17.01,-3.853 ; JP17.1@17.189,-3.673 ccw(c15.902,-4.96) 15.902,-3.14 cw(c15.902,-4.96) JP17.1@17.189,-3.673 ; JP17.1@17.189,-3.673 ccw(c16.155,-4.708) 16.155,-3.244 cw(c16.155,-4.708) JP17.1@17.189,-3.673 ; JP17.1@17.189,-3.673 ccw(c16.554,-4.308) 16.554,-3.41 cw(c16.554,-4.308) JP17.1@17.189,-3.673 ; pad.2@2.469,-3.443 ccw(c3,-2.912) 3,-3.662 cw(c3,-2.912) pad.2@2.469,-3.443 ; 16.098,-3.85 ccw(c16.098,-2.56) 17.01,-3.472 cw(c16.098,-2.56) 16.098,-3.85 ; 16.516,-3.14 cw(c16.516,-4.347) 17.369,-3.494 ccw(c16.516,-4.347) 16.516,-3.14
  Top Layer w0.4: pad.2@2.232,-3.952 cw(c2.933,-4.653) pad.2@2.933,-3.662
  Top Layer w0.6: pad.2@2.05,-4.075 cw(c1.145,-4.98) D3.2@2.425,-4.98
NetJP8_2: JP17.2 Q1.3 | length 31
  Top Layer w0.254: JP17.2@18.01,-7.29 18.17,-7.13 19.78,-7.13 20.116,-6.794 Q1.3@20.246,-6.794 20.246,-6.756 19.94,-6.45 18.26,-6.45 JP17.2@18.05,-6.24 ; JP17.2@18.02,-6.4 18.03,-6.4 18.14,-6.51 ; JP17.2@17.411,-6.752 ccw(c18.323,-5.839) 18.323,-7.13 cw(c18.323,-5.839) JP17.2@17.411,-6.752 ; JP17.2@17.59,-6.572 ccw(c18.937,-5.226) 18.937,-7.13 cw(c18.937,-5.226) JP17.2@17.59,-6.572 ; JP17.2@17.77,-6.393 ccw(c19.55,-4.613) 19.55,-7.13 cw(c19.55,-4.613) JP17.2@17.77,-6.393 ; 18.696,-6.45 cw(c18.696,-8.319) 20.018,-6.997 ccw(c18.696,-8.319) 18.696,-6.45 ; 18.715,-7.13 ccw(c18.715,-5.288) 20.018,-6.591 cw(c18.715,-5.288) 18.715,-7.13 ; 19.309,-6.45 cw(c19.309,-7.706) 20.197,-6.818 ccw(c19.309,-7.706) 19.309,-6.45 ; 19.329,-7.13 ccw(c19.329,-5.902) 20.197,-6.77 cw(c19.329,-5.902) 19.329,-7.13 ; Q1.3@19.804,-7.106 ccw(c19.517,-6.819) 19.923,-6.819 cw(c19.517,-6.819) Q1.3@19.804,-7.106 ; Q1.3@19.922,-6.45 cw(c19.922,-7.092) 20.377,-6.638 ccw(c19.922,-7.092) Q1.3@19.922,-6.45
  Top Layer w0.6: JP17.2@17.35,-6.794 Q1.3@20.246,-6.794 ; JP17.2@17.647,-7.01 cw(c18.169,-7.531) 18.169,-6.794 ccw(c18.169,-7.531) JP17.2@17.647,-7.01 ; JP17.2@17.647,-6.515 ccw(c18.321,-5.841) 18.321,-6.794 cw(c18.321,-5.841) JP17.2@17.647,-6.515
NetJP14_1: 
NetJP32_1: 
NetQ1_1: Q1.1 R11.1 R12.1 | length 70.5
  Top Layer w0.254: 18.98,-9.93 18.98,-10.1 ; 19.05,-10.05 19.3,-10.3 20.18,-10.3 ; Q1.1@19.15,-9.54 19.15,-9.94 19.387,-10.177 19.397,-10.177 ; Q1.1@19.196,-9.144 Q1.1@19.296,-9.144 ; Q1.1@19.47,-9.47 19.47,-10.02 19.62,-10.17 ; Q1.1@19.62,-9.5 19.62,-10 19.92,-10.3 20.34,-10.3 ; 19.85,-10.3 19.18,-10.3 18.98,-10.1 ; 24.7,-10.3 24.83,-10.3 25.22,-9.91 25.22,-9.62 ; R12.1@25.4,-7.51 25.4,-9.98 25.08,-10.3 ; R12.1@25.4,-7.325 25.4,-7.37 R12.1@25.61,-7.58 ; R12.1@25.417,-7.403 25.417,-7.423 R12.1@25.22,-7.62 ; 18.98,-10.1 18.98,-9.47 19.296,-9.154 Q1.1@19.296,-9.144 ; 18.98,-10.1 19.34,-10.46 25.17,-10.46 25.61,-10.02 ; Q1.1@19.068,-9.397 cw(c18.869,-9.596) 19.15,-9.596 ccw(c18.869,-9.596) Q1.1@19.068,-9.397 ; Q1.1@19.068,-9.397 cw(c18.516,-9.949) 19.296,-9.949 ; Q1.1@19.068,-9.397 cw(c18.516,-9.949) 19.296,-9.949 ; 19.296,-9.949 cw(c20.076,-9.949) 19.524,-9.397 ccw(c20.076,-9.949) 19.296,-9.949 ; Q1.1@19.296,-9.144 19.296,-10.076 19.52,-10.3 25.08,-10.3 ; 25.08,-10.3 25.22,-10.16 R12.1@25.22,-7.62 ; 25.08,-10.3 25.33,-10.3 25.61,-10.02 ; R12.1@25.22,-7.62 ccw(c26.184,-7.62) 25.554,-8.35 cw(c26.184,-7.62) R12.1@25.22,-7.62 ; R12.1@25.277,-7.593 cw(c24.98,-7.89) 25.4,-7.89 ccw(c24.98,-7.89) R12.1@25.277,-7.593 ; R12.1@25.277,-7.593 cw(c24.473,-8.397) 25.61,-8.397 ccw(c24.473,-8.397) R12.1@25.277,-7.593 ; R11.1@25.285,-8.74 cw(c25.007,-9.018) 25.4,-9.018 ccw(c25.007,-9.018) R11.1@25.285,-8.74 ; R11.1@25.285,-8.74 cw(c24.5,-9.525) 25.61,-9.525 ccw(c24.5,-9.525) R11.1@25.285,-8.74 ; R12.1@25.557,-7.593 ccw(c25.936,-7.972) 25.4,-7.972 cw(c25.936,-7.972) R12.1@25.557,-7.593 ; R12.1@25.557,-7.593 ccw(c26.371,-8.407) 25.22,-8.407 cw(c26.371,-8.407) R12.1@25.557,-7.593 ; R11.1@25.565,-8.74 ccw(c25.963,-9.138) 25.4,-9.138 cw(c25.963,-9.138) R11.1@25.565,-8.74 ; R11.1@25.565,-8.74 ccw(c26.398,-9.573) 25.22,-9.573 cw(c26.398,-9.573) R11.1@25.565,-8.74 ; 25.61,-10.02 R12.1@25.61,-7.58 ; R12.1@25.61,-7.58 cw(c24.512,-7.58) 25.285,-8.359 ccw(c24.512,-7.58) R12.1@25.61,-7.58 ; 18.98,-10.152 cw(c19.733,-10.152) 19.427,-9.464 ccw(c19.733,-10.152) 18.98,-10.152 ; 18.98,-9.761 cw(c19.559,-9.761) 19.324,-9.232 ccw(c19.559,-9.761) 18.98,-9.761 ; Q1.1@19.132,-9.447 cw(c18.786,-10.038) 19.47,-10.038 ccw(c18.786,-10.038) Q1.1@19.132,-9.447 ; 19.15,-9.954 cw(c19.718,-9.954) 19.449,-9.453 ccw(c19.718,-9.954) 19.15,-9.954 ; Q1.1@19.196,-9.476 cw(c19.005,-10.061) 19.62,-10.061 ccw(c19.005,-10.061) Q1.1@19.196,-9.476 ; Q1.1@19.261,-9.228 cw(c19.046,-9.594) 19.47,-9.594 ccw(c19.046,-9.594) Q1.1@19.261,-9.228 ; Q1.1@19.275,-9.235 cw(c19.119,-9.711) 19.62,-9.711 ccw(c19.119,-9.711) Q1.1@19.275,-9.235 ; 25.22,-8.96 cw(c25.785,-8.96) 25.385,-8.56 ccw(c25.785,-8.96) 25.22,-8.96 ; 25.22,-8.175 ccw(c25.706,-8.175) 25.388,-8.542 cw(c25.706,-8.175) 25.22,-8.175 ; 25.22,-7.793 cw(c25.757,-7.793) 25.377,-7.413 ccw(c25.757,-7.793) 25.22,-7.793 ; R11.1@25.285,-8.36 ccw(c25.007,-8.082) 25.4,-8.082 cw(c25.007,-8.082) R11.1@25.285,-8.36 ; 25.4,-7.962 ccw(c25.963,-7.962) 25.565,-8.36 cw(c25.963,-7.962) 25.4,-7.962 ; R12.1@25.457,-7.413 cw(c25.086,-7.784) 25.61,-7.784 ccw(c25.086,-7.784) R12.1@25.457,-7.413 ; R11.1@25.464,-8.54 ccw(c25.117,-8.19) 25.61,-8.19 cw(c25.117,-8.19) R11.1@25.464,-8.54 ; R11.1@25.465,-8.56 cw(c25.114,-8.911) 25.61,-8.911 ccw(c25.114,-8.911) R11.1@25.465,-8.56
  Top Layer w0.4: R11.1@25.317,-8.663 cw(c24.974,-8.86) 25.356,-8.963 ; R11.1@25.4,-8.8 R12.1@25.4,-7.325 ; 25.4,-8.138 ccw(c25.787,-8.138) R11.1@25.513,-8.412 ; 25.4,-8.138 ccw(c25.787,-8.138) R11.1@25.513,-8.412 ; 25.4,-8.138 ccw(c25.787,-8.138) R11.1@25.513,-8.412 ; 25.4,-8.138 ccw(c25.787,-8.138) R11.1@25.513,-8.412 ; 25.4,-8.138 ccw(c25.787,-8.138) R11.1@25.513,-8.412 ; 25.4,-8.138 ccw(c25.787,-8.138) R11.1@25.513,-8.412 ; 25.4,-8.138 ccw(c25.787,-8.138) R11.1@25.513,-8.412 ; 25.4,-8.138 ccw(c25.787,-8.138) R11.1@25.513,-8.412 ; 25.4,-8.138 ccw(c25.787,-8.138) R11.1@25.513,-8.412 ; 25.4,-8.138 ccw(c25.787,-8.138) R11.1@25.513,-8.412 ; 25.4,-7.796 cw(c25.76,-7.796) R12.1@25.505,-7.541 ; 25.4,-7.796 cw(c25.76,-7.796) R12.1@25.505,-7.541 ; 25.4,-7.796 cw(c25.76,-7.796) R12.1@25.505,-7.541 ; 25.4,-7.796 cw(c25.76,-7.796) R12.1@25.505,-7.541 ; 25.4,-7.796 cw(c25.76,-7.796) R12.1@25.505,-7.541 ; 25.4,-7.796 cw(c25.76,-7.796) R12.1@25.505,-7.541 ; 25.4,-7.796 cw(c25.76,-7.796) R12.1@25.505,-7.541 ; 25.4,-7.796 cw(c25.76,-7.796) R12.1@25.505,-7.541 ; 25.4,-7.796 cw(c25.76,-7.796) R12.1@25.505,-7.541 ; 25.4,-7.796 cw(c25.76,-7.796) R12.1@25.505,-7.541
NetQ1_3: Q1.2 R9.2 R10.2 | length 84.3
  Top Layer w0.254: Q1.2@21.16,-9.36 21.5,-9.36 R9.2@22.02,-8.84 ; Q1.2@21.176,-9.144 21.176,-9.004 21.88,-8.3 R10.2@23.91,-8.3 ; Q1.2@21.442,-8.738 21.662,-8.738 ; Q1.2@21.5,-9.09 21.93,-8.66 ; Q1.2@21.6,-9.49 22.14,-8.95 R10.2@23.74,-8.95 ; R10.2@23.71,-8.66 21.93,-8.66 ; R10.2@23.79,-8.51 21.89,-8.51 ; R10.2@24,-8.625 24,-8.69 R10.2@23.74,-8.95 ; Q1.2@21.499,-9.119 cw(c22.555,-9.119) 21.808,-8.372 ccw(c22.555,-9.119) Q1.2@21.499,-9.119 ; Q1.2@21.499,-9.119 cw(c22.024,-9.119) 21.652,-8.748 ; Q1.2@21.499,-9.119 cw(c22.024,-9.119) 21.652,-8.748 ; Q1.2@21.499,-9.119 cw(c22.024,-9.119) 21.652,-8.748 ; Q1.2@21.499,-9.119 cw(c22.024,-9.119) 21.652,-8.748 ; 21.662,-8.738 cw(c21.415,-8.492) 21.291,-8.817 ccw(c21.415,-8.492) 21.662,-8.738 ; 21.662,-8.738 21.89,-8.51 ; 21.89,-8.51 cw(c21.89,-8.764) 22.137,-8.703 ccw(c21.89,-8.764) 21.89,-8.51 ; 21.89,-8.51 cw(c21.199,-7.819) 21.181,-8.796 ccw(c21.199,-7.819) 21.89,-8.51 ; 21.93,-8.66 cw(c21.93,-8.95) 22.176,-8.796 ccw(c21.93,-8.95) 21.93,-8.66 ; 21.93,-8.66 ccw(c21.93,-8.426) 22.148,-8.51 cw(c21.93,-8.426) 21.93,-8.66 ; 21.93,-8.66 cw(c21.481,-8.211) 21.279,-8.813 ccw(c21.481,-8.211) 21.93,-8.66 ; R9.2@22.02,-8.84 cw(c21.684,-8.504) 21.381,-8.87 ccw(c21.684,-8.504) R9.2@22.02,-8.84 ; R9.2@22.02,-8.84 R10.2@23.63,-8.84 ; R9.2@22.45,-8.948 ccw(c22.45,-10.247) 21.532,-9.328 cw(c22.45,-10.247) R9.2@22.45,-8.948 ; R9.2@22.45,-8.948 ccw(c22.45,-9.692) 21.924,-9.166 cw(c22.45,-9.692) R9.2@22.45,-8.948 ; R9.2@22.728,-8.853 cw(c23.557,-9.682) 23.557,-8.51 ccw(c23.557,-9.682) R9.2@22.728,-8.853 ; R9.2@22.728,-8.853 cw(c23.195,-9.32) 23.195,-8.66 ccw(c23.195,-9.32) R9.2@22.728,-8.853 ; R9.2@22.728,-8.397 ccw(c23.002,-8.123) 23.002,-8.51 cw(c23.002,-8.123) R9.2@22.728,-8.397 ; R9.2@22.728,-8.397 ccw(c23.364,-7.761) 23.364,-8.66 cw(c23.364,-7.761) R9.2@22.728,-8.397 ; R10.2@23.63,-8.84 cw(c23.63,-7.707) 22.751,-8.421 ccw(c23.63,-7.707) R10.2@23.63,-8.84 ; R10.2@23.74,-8.95 cw(c23.74,-7.763) 22.765,-8.441 ccw(c23.74,-7.763) R10.2@23.74,-8.95 ; R10.2@23.747,-8.853 ccw(c22.918,-9.682) 22.918,-8.51 cw(c22.918,-9.682) R10.2@23.747,-8.853 ; R10.2@23.747,-8.853 ccw(c22.411,-10.189) 22.411,-8.3 cw(c22.411,-10.189) R10.2@23.747,-8.853 ; R10.2@23.747,-8.853 ccw(c23.28,-9.32) 23.28,-8.66 cw(c23.28,-9.32) R10.2@23.747,-8.853 ; R10.2@23.747,-8.397 cw(c22.411,-7.061) 22.411,-8.95 ccw(c22.411,-7.061) R10.2@23.747,-8.397 ; R10.2@23.747,-8.397 cw(c23.473,-8.123) 23.473,-8.51 ccw(c23.473,-8.123) R10.2@23.747,-8.397 ; R10.2@23.747,-8.397 cw(c23.111,-7.761) 23.111,-8.66 ccw(c23.111,-7.761) R10.2@23.747,-8.397 ; R10.2@23.747,-8.397 cw(c22.676,-7.326) 22.676,-8.84 ccw(c22.676,-7.326) R10.2@23.747,-8.397 ; R10.2@23.91,-8.3 ccw(c23.91,-9.835) 22.745,-8.835 cw(c23.91,-9.835) R10.2@23.91,-8.3 ; R10.2@23.926,-8.674 ccw(c23.531,-9.069) 23.531,-8.51 cw(c23.531,-9.069) R10.2@23.926,-8.674 ; R10.2@23.926,-8.674 ccw(c23.024,-9.576) 23.024,-8.3 cw(c23.024,-9.576) R10.2@23.926,-8.674 ; R10.2@23.926,-8.576 cw(c23.024,-7.674) 23.024,-8.95 ccw(c23.024,-7.674) R10.2@23.926,-8.576 ; R10.2@23.926,-8.576 cw(c23.289,-7.939) 23.289,-8.84 ccw(c23.289,-7.939) R10.2@23.926,-8.576 ; Q1.2@21.058,-9.262 ccw(c21.327,-8.936) 21.625,-9.235 cw(c21.327,-8.936) Q1.2@21.058,-9.262 ; Q1.2@21.176,-8.796 ccw(c21.176,-8.293) 21.531,-8.649 cw(c21.176,-8.293) Q1.2@21.176,-8.796 ; Q1.2@21.198,-9.054 ccw(c21.335,-8.645) 21.64,-8.95 cw(c21.335,-8.645) Q1.2@21.198,-9.054 ; Q1.2@21.22,-9.066 ccw(c21.505,-8.72) 21.823,-9.037 cw(c21.505,-8.72) Q1.2@21.22,-9.066 ; Q1.2@21.405,-8.775 cw(c22.257,-9.627) 22.485,-8.443 ccw(c22.257,-9.627) Q1.2@21.405,-8.775 ; Q1.2@21.574,-8.826 cw(c22.094,-9.345) 22.419,-8.687 ccw(c22.094,-9.345) Q1.2@21.574,-8.826 ; Q1.2@21.62,-8.97 cw(c22.309,-9.66) 22.441,-8.693 ccw(c22.309,-9.66) Q1.2@21.62,-8.97 ; 21.688,-8.902 cw(c21.982,-9.197) 22.245,-8.875 ccw(c21.982,-9.197) 21.688,-8.902 ; 21.825,-8.575 cw(c22.259,-9.01) 22.532,-8.459 ccw(c22.259,-9.01) 21.825,-8.575 ; 21.886,-8.704 cw(c22.16,-8.979) 22.406,-8.678 ccw(c22.16,-8.979) 21.886,-8.704 ; 21.888,-9.202 ccw(c21.311,-8.625) 22.127,-8.625 cw(c21.311,-8.625) 21.888,-9.202 ; 21.948,-8.51 ccw(c21.948,-8.123) 22.222,-8.397 cw(c21.948,-8.123) 21.948,-8.51 ; 21.965,-8.895 cw(c22.45,-9.38) 22.45,-8.694 ccw(c22.45,-9.38) 21.965,-8.895 ; 21.982,-8.608 cw(c22.396,-9.022) 22.475,-8.442 ccw(c22.396,-9.022) 21.982,-8.608 ; R9.2@22.549,-8.674 cw(c22.944,-9.069) 22.944,-8.51 ccw(c22.944,-9.069) R9.2@22.549,-8.674 ; R9.2@22.552,-8.67 cw(c23.357,-9.361) 23.357,-8.3 ccw(c23.357,-9.361) R9.2@22.552,-8.67 ; R9.2@22.554,-8.582 ccw(c23.096,-8.141) 23.096,-8.84 cw(c23.096,-8.141) R9.2@22.554,-8.582 ; R9.2@22.557,-8.586 ccw(c23.254,-8.101) 23.254,-8.95 cw(c23.254,-8.101) R9.2@22.557,-8.586 ; R10.2@23.637,-8.95 ccw(c23.637,-8.287) 24.106,-8.756 cw(c23.637,-8.287) R10.2@23.637,-8.95 ; R10.2@23.637,-8.3 cw(c23.637,-8.963) 24.106,-8.494 ccw(c23.637,-8.963) R10.2@23.637,-8.3
NetQ2_S: Q2.2 Q3.2 U3.1 | length 45.4
  Top Layer w0.254: Q3.2@196.97,17.69 198.324,17.69 Q2.2@198.388,17.625 ; U3.1@196.998,16.465 196.998,17.148 Q3.2@197.13,17.28 ; Q3.2@197.26,17.45 Q2.2@198.05,17.45 ; Q3.2@197.48,17.79 197.81,17.79 ; Q2.2@198.14,17.58 197.058,17.58 197.058,17.768 Q3.2@197.25,17.96 ; Q3.2@197.13,17.28 ccw(c197.13,18.509) 198.127,17.79 cw(c197.13,18.509) Q3.2@197.13,17.28 ; Q3.2@197.13,17.28 Q2.2@198.04,17.28 ; Q3.2@197.25,17.96 cw(c197.25,16.942) 198.114,17.48 ccw(c197.25,16.942) Q3.2@197.25,17.96 ; Q3.2@197.25,17.96 Q2.2@198.41,17.96 ; Q3.2@197.274,17.366 cw(c197.791,16.85) 197.791,17.58 ccw(c197.791,16.85) Q3.2@197.274,17.366 ; Q3.2@197.274,17.366 cw(c197.477,17.164) 197.477,17.45 ccw(c197.477,17.164) Q3.2@197.274,17.366 ; Q3.2@197.274,17.366 ccw(c197.943,16.697) 196.998,16.697 cw(c197.943,16.697) Q3.2@197.274,17.366 ; Q3.2@197.274,17.873 ccw(c197.475,18.073) 197.475,17.79 cw(c197.475,18.073) Q3.2@197.274,17.873 ; Q3.2@197.274,17.873 ccw(c197.716,18.314) 197.716,17.69 cw(c197.716,18.314) Q3.2@197.274,17.873 ; 197.81,17.79 ccw(c197.81,17.256) 197.334,17.498 cw(c197.81,17.256) 197.81,17.79 ; Q2.2@198.04,17.28 cw(c198.04,18.05) 197.34,17.729 ccw(c198.04,18.05) Q2.2@198.04,17.28 ; Q2.2@198.05,17.45 cw(c198.05,18.439) 197.293,17.802 ccw(c198.05,18.439) Q2.2@198.05,17.45 ; Q2.2@198.41,17.96 ccw(c198.41,16.507) 197.294,17.438 cw(c198.41,16.507) Q2.2@198.41,17.96 ; Q3.2@196.818,17.366 cw(c196.384,16.932) 196.998,16.932 ccw(c196.384,16.932) Q3.2@196.818,17.366 ; Q3.2@197.099,17.6 cw(c197.867,16.96) 197.867,17.96 ccw(c197.867,16.96) Q3.2@197.099,17.6 ; Q3.2@197.099,17.639 ccw(c197.505,17.98) 197.505,17.45 cw(c197.505,17.98) Q3.2@197.099,17.639 ; Q3.2@197.109,17.623 ccw(c197.644,17.869) 197.644,17.28 cw(c197.644,17.869) Q3.2@197.109,17.623 ; Q3.2@197.26,17.45 ccw(c197.26,18.708) 198.158,17.827 cw(c197.26,18.708) Q3.2@197.26,17.45 ; Q3.2@197.274,17.416 cw(c197.936,16.755) 197.936,17.69 ccw(c197.936,16.755) Q3.2@197.274,17.416 ; Q3.2@197.274,17.823 ccw(c197.861,18.409) 197.861,17.58 cw(c197.861,18.409) Q3.2@197.274,17.823 ; 197.513,17.69 cw(c197.513,16.775) 198.16,17.422 ccw(c197.513,16.775) 197.513,17.69 ; 197.559,17.58 ccw(c197.559,18.43) 198.16,17.829 cw(c197.559,18.43) 197.559,17.58 ; 197.627,17.28 ccw(c197.627,18.15) 198.332,17.641 cw(c197.627,18.15) 197.627,17.28 ; 197.658,17.58 cw(c197.658,16.87) 198.16,17.372 ccw(c197.658,16.87) 197.658,17.58 ; 197.704,17.69 ccw(c197.704,18.335) 198.16,17.879 cw(c197.704,18.335) 197.704,17.69 ; 197.707,17.96 cw(c197.707,17.227) 198.33,17.614 ccw(c197.707,17.227) 197.707,17.96 ; 197.865,17.45 ccw(c197.865,18.114) 198.339,17.649 cw(c197.865,18.114) 197.865,17.45
  Top Layer w0.305: U3.1@196.998,16.465 196.998,17.435 cw(c197.202,17.435) Q3.2@197.057,17.58 ; Q3.2@196.836,17.384 cw(c196.445,16.993) 196.998,16.993 ccw(c196.445,16.993) Q3.2@196.836,17.384 ; 196.998,16.759 cw(c197.882,16.759) 197.257,17.384 ccw(c197.882,16.759) 196.998,16.759
NetQ3_1: Q3.1 U3.2 | length 4.1
  Top Layer w0.305: Q3.1@195.065,17.67 cw(c195.065,17.362) 195.283,17.58 U3.2@196.398,16.465 ; Q3.1@195.166,17.297 cw(c195.166,16.333) 195.848,17.015 ccw(c195.166,16.333) Q3.1@195.166,17.297 ; Q3.1@195.464,17.595 ccw(c195.937,17.595) 195.603,17.26 cw(c195.937,17.595) Q3.1@195.464,17.595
